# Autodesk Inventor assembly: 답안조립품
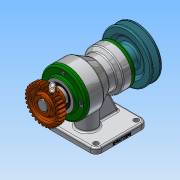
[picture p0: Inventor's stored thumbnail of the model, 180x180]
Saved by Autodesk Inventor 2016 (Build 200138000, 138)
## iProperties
Created: 2019-01
Part Number: 답안조립품
Material: 일반
Document SubType Name: Assembly
Designer: Administrator
Author: Administrator
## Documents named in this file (15)
- C:\Users\Administrator\Desktop\490107V1018\답안조립품.iam
- C:\Users\Administrator\Desktop\490107V1018\본체.ipt
- C:\Users\Administrator\Desktop\490107V1018\축.ipt
- C:\Users\Administrator\Desktop\490107V1018\키 6 x 6 x 18.ipt
- C:\Users\Administrator\Desktop\490107V1018\스퍼기어.ipt
- C:\Users\Administrator\Desktop\490107V1018\멈춤나사 M3.ipt
- C:\Users\Administrator\Desktop\490107V1018\오일 실 17 30 8.ipt
- C:\Users\Administrator\Desktop\490107V1018\앞커버.ipt
- C:\Users\Administrator\Desktop\490107V1018\오일 실 25 38 8.ipt
- C:\Users\Administrator\Desktop\490107V1018\볼트 M4.ipt
- C:\Users\Administrator\Desktop\490107V1018\베어링 6205.ipt
- C:\Users\Administrator\Desktop\490107V1018\베어링 6203.ipt
- C:\Users\Administrator\Desktop\490107V1018\뒤커버.ipt
- C:\Users\Administrator\Desktop\490107V1018\키 5 x 5 x 20.ipt
- C:\Users\Administrator\Desktop\490107V1018\V-벨트풀리.ipt
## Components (1 placed, 1 different names)
1. V-벨트풀리:1 — 플러쉬:2
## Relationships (1: Flush 1)
- 플러쉬:2 [Flush]: V-벨트풀리:1
